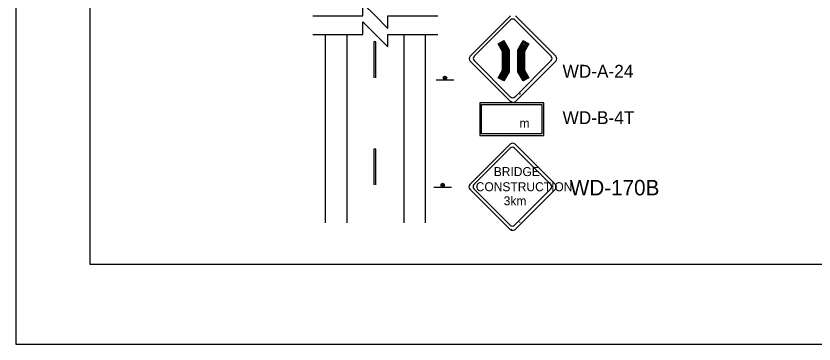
# Model space of a CAD drawing. Extents: x 2179 to 2395, y 134 to 413.
# Drawn here: x 2178.7 to 2286.7, y 133.8 to 178.2 of the extents above; entities that cross this region are included whole.
import ezdxf

# ---------------------------------------------------------------- set-up
doc = ezdxf.new("R2010")
doc.units = 0
for name, color, linetype in [('Level 10', 7, 'Continuous'), ('Level 2', 7, 'Continuous'), ('Level 20', 7, 'Continuous'), ('Level 44', 7, 'Continuous'), ('Level 60', 7, 'Continuous')]:
    doc.layers.add(name, color=color, linetype=linetype)

# ---------------------------------------------------------------- blocks, each defined once
blk = doc.blocks.new('BREAK')
at = {"layer": 'Level 20'}
blk.add_lwpolyline([(-12.499, 0), (-2.5, 0), (-2.5, 2.5), (0, 0), (2.501, -2.501), (2.501, 0), (12.501, 0)], dxfattribs=at)
blk = doc.blocks.new('BR')
at = {"layer": 'Level 20', "xscale": 0.4837996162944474, "yscale": 0.4837996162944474}
blk.add_blockref('BREAK', (1.209, 0), dxfattribs=at)

msp = doc.modelspace()

# ---------------------------------------------------------------- linework, layer by layer
at = {"layer": 'Level 10'}
for p, q in [((2220.64, 150.21), (2220.64, 175.74)), ((2223.55, 150.21), (2223.55, 175.74)), ((2231.29, 150.21), (2231.29, 175.74)), ((2234.19, 150.21), (2234.19, 175.74))]:
    msp.add_line(p, q, dxfattribs=at)
msp.add_lwpolyline([(2241.76, 166.23), (2249.9, 166.23), (2249.9, 162.28), (2241.76, 162.28)], close=True, dxfattribs=at)
at = {"layer": 'Level 2'}
for p, q in [((2227.17, 174.71), (2227.17, 169.87)), ((2227.46, 174.71), (2227.17, 174.71)), ((2227.46, 169.87), (2227.46, 174.71)), ((2247.02, 167.72), (2246.91, 167.61)), ((2245.9, 166.7), (2245.8, 166.6)), ((2227.17, 160.2), (2227.17, 155.36)), ((2227.46, 160.2), (2227.17, 160.2)), ((2227.46, 155.36), (2227.46, 160.2)), ((2246.98, 150.34), (2246.88, 150.24)), ((2245.87, 149.32), (2245.76, 149.22))]:
    msp.add_line(p, q, dxfattribs=at)
at = {"layer": 'Level 44'}
for p, q in [((2245.68, 178.24), (2240.2, 172.77)), ((2251.8, 172.77), (2246.33, 178.24)), ((2240.75, 172.77), (2245.68, 177.69)), ((2246.26, 177.69), (2251.19, 172.77)), ((2240.2, 172.12), (2245.68, 166.65)), ((2240.21, 172.12), (2240.2, 172.12)), ((2245.68, 167.25), (2240.75, 172.18)), ((2251.19, 172.18), (2246.26, 167.25)), ((2246.33, 166.65), (2251.8, 172.12)), ((2235.59, 169.58), (2237.99, 169.58)), ((2245.64, 160.86), (2240.16, 155.39)), ((2240.71, 155.39), (2245.64, 160.31)), ((2246.22, 160.31), (2251.15, 155.39)), ((2251.76, 155.39), (2246.29, 160.86)), ((2235.29, 155.04), (2237.69, 155.04)), ((2240.16, 154.74), (2245.64, 149.27)), ((2240.17, 154.74), (2240.16, 154.74)), ((2245.64, 149.88), (2240.71, 154.8)), ((2251.15, 154.8), (2246.22, 149.88)), ((2246.29, 149.27), (2251.76, 154.74))]:
    msp.add_line(p, q, dxfattribs=at)
for points in [[(2243.98, 169.86), (2244.58, 170.9), (2244.58, 173.42), (2243.98, 174.46), (2244.75, 174.9), (2245.47, 173.66), (2245.47, 170.66), (2244.75, 169.42), (2243.98, 169.86), (2244.12, 169.89), (2244.69, 170.87), (2244.69, 173.44), (2244.12, 174.42), (2244.71, 174.75), (2245.36, 173.63), (2245.36, 170.68), (2244.7, 169.56), (2244.12, 169.89), (2244.28, 169.94), (2244.8, 170.83), (2244.8, 173.47), (2244.28, 174.38), (2244.67, 174.6), (2245.25, 173.59), (2245.25, 170.72), (2244.67, 169.71), (2244.28, 169.94), (2244.43, 169.97), (2244.91, 170.81), (2244.91, 173.5), (2244.43, 174.33), (2244.63, 174.45), (2245.14, 173.57), (2245.14, 170.75), (2244.62, 169.86), (2244.43, 169.97), (2244.58, 170.02), (2244.68, 169.96), (2244.58, 170.02), (2245.02, 170.78), (2245.02, 173.53), (2244.58, 174.29), (2244.68, 174.35), (2244.75, 174.9)], [(2247.39, 169.42), (2246.67, 170.66), (2246.67, 173.66), (2247.39, 174.9), (2248.16, 174.46), (2247.56, 173.42), (2247.56, 170.9), (2248.16, 169.86), (2247.39, 169.42), (2247.43, 169.59), (2246.8, 170.69), (2246.8, 173.62), (2247.44, 174.72), (2247.99, 174.4), (2247.43, 173.45), (2247.43, 170.86), (2247.99, 169.91), (2247.43, 169.59), (2247.48, 169.76), (2246.92, 170.72), (2246.92, 173.59), (2247.49, 174.55), (2247.81, 174.36), (2247.31, 173.48), (2247.31, 170.83), (2247.81, 169.95), (2247.48, 169.76), (2247.53, 169.93), (2247.06, 170.76), (2247.06, 173.55), (2247.53, 174.38), (2247.64, 174.31), (2247.17, 173.52), (2247.18, 170.79), (2247.64, 170), (2247.53, 169.93), (2248.16, 169.86)]]:
    msp.add_lwpolyline(points, dxfattribs=at)
msp.add_lwpolyline([(2250.18, 166.46), (2241.51, 166.46), (2241.51, 162.04), (2250.18, 162.04)], close=True, dxfattribs=at)
for centre, radius in [((2236.8, 169.85), 0.24), ((2236.8, 169.85), 0.12), ((2236.5, 155.31), 0.24), ((2236.5, 155.31), 0.12)]:
    msp.add_circle(centre, radius, dxfattribs=at)
for centre, radius, start, end in [((2245.97, 177.4), 0.412, 45, 135), ((2240.53, 172.45), 0.458, 135, 225), ((2241.04, 172.47), 0.412, 135, 225), ((2250.9, 172.47), 0.412, 315, 45), ((2251.47, 172.45), 0.458, 315, 45), ((2245.97, 167.55), 0.412, 225, 315), ((2246, 166.97), 0.458, 225, 315), ((2245.96, 160.54), 0.458, 45, 135), ((2245.93, 160.02), 0.412, 45, 135), ((2240.49, 155.07), 0.458, 135, 225), ((2241.01, 155.1), 0.412, 135, 225), ((2250.86, 155.1), 0.412, 315, 45), ((2251.44, 155.07), 0.458, 315, 45), ((2245.93, 150.17), 0.412, 225, 315), ((2245.96, 149.6), 0.458, 225, 315)]:
    msp.add_arc(centre, radius, start, end, dxfattribs=at)
at = {"layer": 'Level 60'}
for p, q in [((2188.75, 144.57), (2188.75, 144.57)), ((2178.75, 133.76), (2178.75, 133.76))]:
    msp.add_line(p, q, dxfattribs=at)
for points in [[(2394.75, 412.76), (2178.75, 412.76), (2178.75, 133.76), (2394.75, 133.76)], [(2375.62, 401.95), (2188.75, 401.95), (2188.75, 144.57), (2375.62, 144.57)]]:
    msp.add_lwpolyline(points, close=True, dxfattribs=at)

# ---------------------------------------------------------------- block references
at = {"layer": 'Level 20', "xscale": 1.4, "yscale": 1.4}
for p in [(2225.69, 178.24), (2225.69, 175.74)]:
    msp.add_blockref('BR', p, dxfattribs=at)

# ---------------------------------------------------------------- texts
at = {"layer": 'Level 10'}
for s, height, p in [('WD-A-24', 1.742, (2252.72, 169.87)), ('WD-B-4T', 1.742, (2252.72, 163.58)), ('WD-170B', 2.09, (2253.7, 153.92))]:
    msp.add_text(s, height=height, dxfattribs=at).set_placement(p)
at = {"layer": 'Level 44'}
for s, height, p in [('m', 1.21, (2246.9, 163.1)), ('CONSTRUCTION', 1.2143, (2240.97, 154.48)), ('3km', 1.214, (2244.75, 152.57))]:
    msp.add_text(s, height=height, dxfattribs=at).set_placement(p)
msp.add_text('BRIDGE', height=1.214, rotation=360, dxfattribs=at).set_placement((2243.41, 156.53))

doc.saveas('drawing.dxf')
